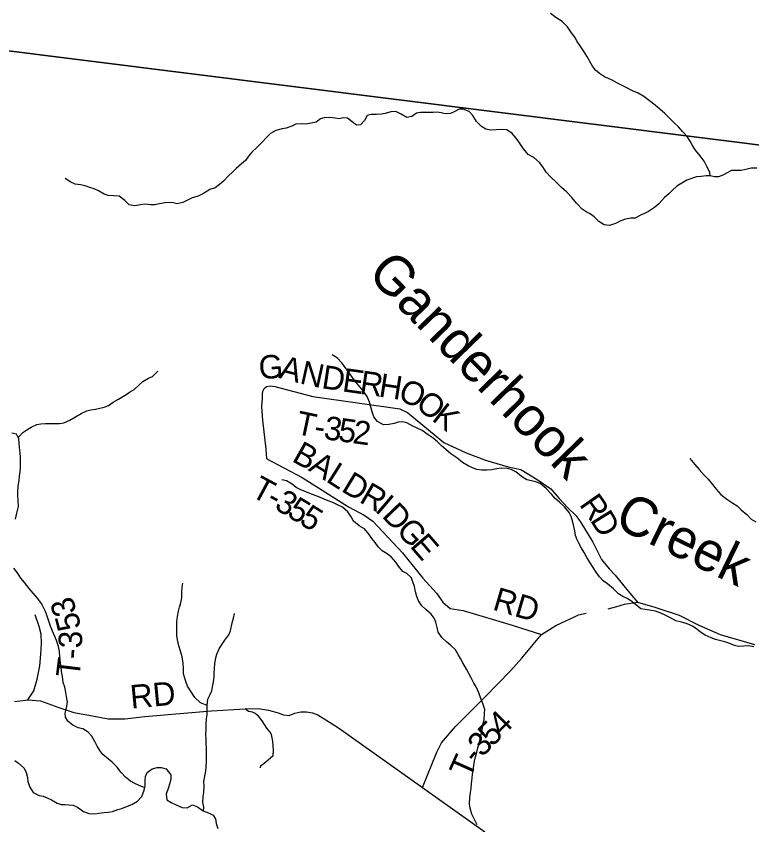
# Model space of a CAD drawing. Extents: x 1578669 to 1989827, y 208020 to 553079.
# Drawn here: x 1803566 to 1812953, y 353651 to 363967 of the extents above; entities that cross this region are included whole.
import ezdxf

# ---------------------------------------------------------------- set-up
doc = ezdxf.new("R2010")
doc.units = 0
for name, color, linetype in [('GM_X_County_Road', 7, 'Continuous'), ('GM_X_County_Road_Text', 7, 'Continuous'), ('GM_X_Minor_River', 7, 'Continuous'), ('GM_X_Minor_River_Text', 7, 'Continuous'), ('GM_X_Township', 7, 'Continuous'), ('GM_X_Township_Road', 7, 'Continuous'), ('GM_X_Township_Road_Text', 7, 'Continuous')]:
    doc.layers.add(name, color=color, linetype=linetype)

msp = doc.modelspace()

# ---------------------------------------------------------------- linework, layer by layer
at = {"layer": 'GM_X_County_Road'}
msp.add_lwpolyline([(1803546, 355225), (1803683, 355242), (1803715, 355245), (1803875, 355234), (1804112, 355146), (1804300, 355084), (1804541, 355040), (1804739, 355003), (1804952, 355003), (1805208, 355031), (1805656, 355072), (1806058, 355103), (1806488, 355130), (1806652, 355134), (1806786, 355114), (1806910, 355080), (1806979, 355056), (1807049, 355047), (1807123, 355074), (1807200, 355091), (1807272, 355093), (1807347, 355080), (1807415, 355056), (1807519, 354992), (1807680, 354890), (1808750, 354127), (1809548, 353563)], dxfattribs=at)
at = {"layer": 'GM_X_Minor_River'}
for points in [[(1812420, 361929), (1812418, 361975), (1812380, 362047), (1812344, 362119), (1812294, 362185), (1812236, 362257), (1812198, 362316), (1812166, 362374), (1812128, 362430), (1812068, 362496), (1812019, 362556), (1811963, 362606), (1811839, 362730), (1811785, 362776), (1811719, 362830), (1811647, 362888), (1811575, 362940), (1811503, 362984), (1811430, 363016), (1811350, 363058), (1811288, 363086), (1811238, 363114), (1811180, 363146), (1811124, 363170), (1811074, 363194), (1811010, 363236), (1810960, 363278), (1810922, 363330), (1810882, 363396), (1810848, 363456), (1810807, 363524), (1810771, 363576), (1810723, 363644), (1810695, 363698), (1810653, 363754), (1810599, 363829), (1810533, 363897), (1810451, 363949), (1810385, 363999)], [(1813015, 362028), (1812943, 362028), (1812893, 362016), (1812815, 361998), (1812765, 362000), (1812695, 361997), (1812639, 361967), (1812581, 361937), (1812529, 361919), (1812478, 361917), (1812420, 361929), (1812370, 361929), (1812306, 361923), (1812248, 361915), (1812194, 361901), (1812122, 361876), (1812058, 361838), (1811998, 361800), (1811946, 361750), (1811896, 361700), (1811840, 361654), (1811766, 361573), (1811712, 361527), (1811634, 361473), (1811584, 361451), (1811532, 361427), (1811464, 361390), (1811408, 361388), (1811341, 361378), (1811283, 361354), (1811213, 361320), (1811137, 361296), (1811069, 361306), (1811001, 361346), (1810943, 361408), (1810889, 361446), (1810839, 361470), (1810787, 361504), (1810715, 361580), (1810658, 361652), (1810594, 361720), (1810526, 361782), (1810456, 361850), (1810390, 361914), (1810328, 361978), (1810284, 362046), (1810244, 362102), (1810170, 362162), (1810101, 362202), (1810039, 362276), (1809987, 362352), (1809947, 362409), (1809895, 362469), (1809827, 362515), (1809761, 362520), (1809691, 362516), (1809619, 362514), (1809557, 362524), (1809502, 362558), (1809440, 362624), (1809392, 362698), (1809346, 362750), (1809268, 362780), (1809218, 362782), (1809164, 362752), (1809110, 362726), (1809040, 362722), (1808988, 362732), (1808938, 362740), (1808888, 362738), (1808832, 362736), (1808775, 362738), (1808725, 362739), (1808675, 362729), (1808613, 362687), (1808549, 362673), (1808477, 362717), (1808409, 362749), (1808347, 362747), (1808273, 362727), (1808223, 362717), (1808165, 362713), (1808097, 362712), (1808045, 362698), (1808011, 362634), (1807961, 362580), (1807909, 362576), (1807854, 362620), (1807792, 362666), (1807740, 362668), (1807688, 362658), (1807638, 362664), (1807570, 362672)], [(1807570, 362672), (1807498, 362670), (1807448, 362655), (1807392, 362613), (1807328, 362601), (1807258, 362587), (1807206, 362593), (1807134, 362589), (1807084, 362563), (1807013, 362539), (1806959, 362530), (1806879, 362508), (1806813, 362468), (1806755, 362416), (1806707, 362364), (1806643, 362297), (1806571, 362231), (1806531, 362181), (1806493, 362125), (1806441, 362081), (1806375, 362022), (1806325, 361978), (1806277, 361928), (1806211, 361860), (1806161, 361818), (1806105, 361778), (1806037, 361755), (1805957, 361705), (1805887, 361671), (1805813, 361649), (1805745, 361617), (1805693, 361589), (1805620, 361572), (1805570, 361584), (1805518, 361588), (1805466, 361584), (1805394, 361574), (1805336, 361560), (1805286, 361562), (1805206, 361568), (1805154, 361560), (1805082, 361548), (1805008, 361560), (1804954, 361614), (1804880, 361672), (1804807, 361676), (1804739, 361677), (1804687, 361697), (1804617, 361737), (1804561, 361763), (1804507, 361783), (1804447, 361801), (1804385, 361817), (1804317, 361823), (1804265, 361847), (1804193, 361895)], [(1808129, 358856), (1808109, 358918), (1808097, 358968), (1808073, 359043), (1808043, 359115), (1807995, 359189), (1807953, 359239), (1807909, 359291), (1807855, 359361), (1807805, 359431), (1807766, 359483), (1807720, 359545), (1807664, 359603), (1807598, 359647)], [(1803590, 358594), (1803606, 358605), (1803650, 358655), (1803700, 358688), (1803758, 358724), (1803830, 358756), (1803880, 358768), (1803938, 358770), (1804002, 358772), (1804069, 358770), (1804119, 358770), (1804173, 358778), (1804251, 358811), (1804323, 358857), (1804397, 358899), (1804467, 358931), (1804519, 358943), (1804579, 358953), (1804633, 358965), (1804689, 358978), (1804745, 359002), (1804805, 359042), (1804871, 359080), (1804955, 359130), (1805011, 359170), (1805071, 359203), (1805129, 359261), (1805183, 359307), (1805254, 359349), (1805306, 359369), (1805374, 359438)], [(1812979, 355921), (1812909, 355935), (1812849, 355929), (1812781, 355926), (1812731, 355938), (1812659, 355968), (1812607, 355986), (1812540, 356002), (1812488, 356014), (1812432, 356036), (1812356, 356072), (1812300, 356110), (1812250, 356146), (1812198, 356186), (1812128, 356214), (1812054, 356236), (1811984, 356254), (1811905, 356294), (1811855, 356322), (1811793, 356352), (1811723, 356378), (1811671, 356384), (1811591, 356396), (1811537, 356408), (1811485, 356448), (1811411, 356508), (1811361, 356538), (1811305, 356564), (1811251, 356596), (1811188, 356660), (1811112, 356724), (1811056, 356762), (1811010, 356814), (1810968, 356872), (1810930, 356932), (1810888, 356994), (1810846, 357060), (1810812, 357124), (1810778, 357182), (1810750, 357234), (1810723, 357287), (1810703, 357341), (1810693, 357403), (1810669, 357511), (1810647, 357583), (1810621, 357637), (1810563, 357707), (1810497, 357767), (1810443, 357815), (1810397, 357867), (1810329, 357941), (1810252, 358005), (1810196, 358025), (1810140, 358039), (1810084, 358051), (1810016, 358093), (1809940, 358155), (1809884, 358183), (1809832, 358195), (1809756, 358201), (1809698, 358191), (1809632, 358179), (1809571, 358173), (1809507, 358175), (1809443, 358185), (1809389, 358203), (1809335, 358229), (1809261, 358273), (1809187, 358331), (1809111, 358383), (1809049, 358439), (1808995, 358485), (1808940, 358537), (1808886, 358583), (1808822, 358627), (1808748, 358679), (1808684, 358711), (1808620, 358741), (1808550, 358779), (1808498, 358791), (1808440, 358787), (1808388, 358770), (1808320, 358756), (1808254, 358754), (1808175, 358796), (1808129, 358856)], [(1803559, 357551), (1803573, 357625), (1803597, 357713), (1803591, 357790), (1803585, 357846), (1803587, 357902), (1803592, 357968), (1803602, 358048), (1803610, 358100), (1803616, 358152), (1803622, 358214), (1803622, 358339), (1803616, 358395), (1803610, 358465), (1803606, 358523), (1803600, 358573), (1803570, 358635), (1803510, 358649)], [(1812162, 358323), (1812227, 358247), (1812283, 358183), (1812345, 358113), (1812395, 358061), (1812453, 357994), (1812499, 357934), (1812559, 357864), (1812635, 357804), (1812711, 357754), (1812764, 357722), (1812818, 357670), (1812890, 357608), (1812944, 357552), (1813006, 357514)], [(1809378, 354176), (1809384, 354244), (1809390, 354298), (1809398, 354350), (1809406, 354407), (1809416, 354461), (1809426, 354517), (1809442, 354577), (1809456, 354631), (1809474, 354691), (1809488, 354749), (1809500, 354805), (1809510, 354864), (1809520, 354924), (1809536, 354996), (1809543, 355072), (1809545, 355124), (1809521, 355198), (1809497, 355264), (1809469, 355333), (1809435, 355409), (1809407, 355459), (1809377, 355519), (1809343, 355581), (1809313, 355637), (1809267, 355719), (1809235, 355771), (1809207, 355823), (1809173, 355881), (1809106, 355941), (1809056, 355985), (1809002, 356037), (1808952, 356108), (1808938, 356166), (1808922, 356234), (1808900, 356288), (1808862, 356338), (1808794, 356398), (1808742, 356446), (1808700, 356510), (1808679, 356564), (1808663, 356622), (1808647, 356692), (1808627, 356750), (1808605, 356806), (1808551, 356855), (1808501, 356883), (1808443, 356949), (1808411, 357001), (1808351, 357071), (1808299, 357109), (1808235, 357147), (1808184, 357195), (1808148, 357253), (1808106, 357305), (1808070, 357355), (1808010, 357425), (1807944, 357465), (1807872, 357525), (1807842, 357579), (1807800, 357643), (1807730, 357701), (1807675, 357727), (1807613, 357757), (1807547, 357785), (1807497, 357807), (1807437, 357829), (1807379, 357853), (1807315, 357877), (1807261, 357899), (1807189, 357927), (1807139, 357955), (1807087, 357995), (1807016, 358037), (1806954, 358051)], [(1805208, 354127), (1805185, 354132), (1805135, 354154), (1805079, 354176), (1805025, 354208), (1804961, 354258), (1804904, 354320), (1804852, 354390), (1804792, 354452), (1804742, 354488), (1804672, 354546), (1804632, 354598), (1804600, 354654), (1804574, 354706), (1804530, 354782), (1804486, 354834), (1804416, 354876), (1804355, 354886), (1804291, 354920), (1804225, 354974), (1804197, 355026), (1804191, 355077), (1804207, 355143), (1804221, 355215), (1804209, 355287), (1804201, 355337), (1804185, 355405), (1804167, 355467), (1804155, 355543), (1804145, 355608), (1804139, 355666), (1804131, 355716), (1804123, 355792), (1804119, 355860), (1804108, 355924), (1804080, 356004), (1804058, 356054), (1804030, 356121), (1804006, 356183), (1803986, 356237), (1803970, 356289), (1803938, 356371), (1803914, 356423), (1803888, 356475), (1803838, 356541), (1803782, 356607), (1803732, 356667), (1803673, 356741), (1803627, 356799), (1803581, 356864), (1803537, 356924)], [(1806003, 355173), (1805917, 355207), (1805847, 355277), (1805799, 355347), (1805753, 355419), (1805725, 355490), (1805703, 355576), (1805699, 355644), (1805696, 355712), (1805684, 355792), (1805662, 355866), (1805640, 355934), (1805624, 356011), (1805616, 356067), (1805614, 356117), (1805614, 356171), (1805616, 356239), (1805624, 356309), (1805636, 356375), (1805650, 356427), (1805666, 356482), (1805678, 356546), (1805680, 356614), (1805684, 356684), (1805694, 356734)], [(1805958, 353826), (1805960, 353876), (1805948, 353937), (1805954, 354011), (1805962, 354063), (1805964, 354145), (1805962, 354203), (1805972, 354273), (1805984, 354337), (1805992, 354394), (1805996, 354448), (1805994, 354506), (1805994, 354626), (1805992, 354694), (1805989, 354754), (1805987, 354804), (1805989, 354873), (1805989, 354925), (1805995, 355001), (1806001, 355053), (1806003, 355129), (1806003, 355179), (1806013, 355253), (1806039, 355304), (1806061, 355360), (1806073, 355410), (1806085, 355474), (1806091, 355538), (1806093, 355590), (1806097, 355642), (1806101, 355709), (1806113, 355779), (1806125, 355829), (1806161, 355905), (1806193, 355955), (1806229, 356005), (1806279, 356074), (1806301, 356126), (1806321, 356226), (1806339, 356288), (1806353, 356348)], [(1803547, 354472), (1803597, 354436), (1803667, 354372), (1803695, 354318), (1803709, 354256), (1803713, 354204), (1803741, 354132), (1803783, 354062), (1803859, 354024), (1803912, 354016), (1803962, 353996), (1804016, 353968), (1804090, 353926), (1804140, 353912), (1804190, 353908), (1804242, 353906), (1804294, 353900), (1804350, 353874), (1804424, 353822), (1804492, 353796), (1804566, 353792), (1804620, 353800), (1804689, 353809), (1804739, 353813), (1804795, 353821), (1804865, 353847), (1804915, 353861), (1804967, 353881), (1805041, 353911), (1805115, 353951), (1805169, 354010), (1805201, 354094), (1805213, 354148), (1805213, 354216), (1805217, 354268), (1805239, 354318), (1805301, 354365), (1805367, 354381), (1805417, 354381), (1805481, 354363), (1805539, 354287), (1805541, 354237), (1805527, 354183), (1805505, 354114), (1805481, 354042), (1805489, 353968), (1805545, 353936), (1805614, 353900), (1805682, 353872), (1805746, 353868), (1805814, 353906), (1805880, 353882), (1805950, 353828), (1806020, 353804), (1806078, 353776), (1806110, 353726), (1806118, 353668), (1806140, 353604)], [(1809450, 353649), (1809414, 353719), (1809382, 353787), (1809358, 353863), (1809350, 353917), (1809356, 353998), (1809364, 354064), (1809370, 354116), (1809378, 354176)]]:
    msp.add_lwpolyline(points, dxfattribs=at)
at = {"layer": 'GM_X_Township'}
for points in [[(1795322, 364551), (1813574, 362259)], [(1816277, 364043), (1816631, 363924), (1816735, 363905), (1816837, 363873), (1816931, 363836), (1817131, 363727), (1817227, 363665), (1817520, 363444), (1817577, 363353), (1817650, 363170), (1817685, 362949), (1817688, 362852), (1817672, 362762), (1817667, 362662), (1817645, 362376), (1817518, 361992), (1817360, 361758), (1813574, 362259), (1795322, 364551)]]:
    msp.add_lwpolyline(points, dxfattribs=at)
at = {"layer": 'GM_X_Township_Road'}
for points in [[(1806765, 358318), (1806754, 358442), (1806715, 358812), (1806702, 358987), (1806707, 359095), (1806709, 359153), (1806719, 359191), (1806732, 359217), (1806760, 359241), (1806808, 359251), (1806866, 359242), (1807351, 359114), (1808463, 358959), (1808559, 358910), (1809022, 358529), (1809307, 358397), (1809553, 358301), (1809842, 358218), (1810006, 358185), (1810212, 358057), (1810390, 357935), (1810494, 357812), (1810599, 357699), (1810713, 357591), (1810771, 357507), (1810923, 357255), (1811034, 357037), (1811132, 356916), (1811210, 356835), (1811375, 356631), (1811494, 356492), (1811715, 356426), (1812026, 356325), (1812278, 356197), (1812550, 356080), (1812987, 355951)], [(1806765, 358318), (1807216, 358082), (1807807, 357708), (1808006, 357602), (1808117, 357525), (1808496, 357121), (1808755, 356796), (1808928, 356604), (1809008, 356491), (1809104, 356410), (1809268, 356383), (1809894, 356199), (1810268, 356080)], [(1811118, 356405), (1811230, 356438), (1811330, 356466), (1811494, 356492)], [(1803715, 355245), (1803792, 355359), (1803833, 355507), (1803869, 355680), (1803880, 355826), (1803891, 355962), (1803885, 356085), (1803860, 356179), (1803807, 356328)], [(1808750, 354127), (1808934, 354577), (1808991, 354697), (1809173, 354903), (1809546, 355281), (1809875, 355617), (1810017, 355775), (1810141, 355924), (1810268, 356080), (1810404, 356164), (1810453, 356193), (1810581, 356251), (1810690, 356303), (1810743, 356329), (1810840, 356351)], [(1806685, 354377), (1806689, 354408), (1806707, 354420), (1806732, 354437), (1806782, 354478), (1806844, 354534), (1806850, 354598), (1806840, 354720), (1806825, 354801), (1806805, 354832), (1806763, 354884), (1806703, 354977), (1806660, 355039), (1806616, 355070), (1806583, 355087), (1806532, 355095), (1806488, 355130)]]:
    msp.add_lwpolyline(points, dxfattribs=at)

# ---------------------------------------------------------------- texts
at = {"layer": 'GM_X_County_Road_Text'}
msp.add_text('RD', height=300, rotation=5.4198, dxfattribs=at).set_placement((1805034, 355132))
at = {"layer": 'GM_X_Minor_River_Text'}
for s, rotation, p in [('Ganderhook', 314.1517, (1808032, 360671)), ('Creek', 334.0199, (1811177, 357464))]:
    msp.add_text(s, height=500, rotation=rotation, dxfattribs=at).set_placement(p)
at = {"layer": 'GM_X_Township_Road_Text'}
for s, rotation, p in [('G', 3.2037, (1806668, 359336)), ('A', 345.4743, (1806907, 359353)), ('N', 347.398, (1807173, 359284)), ('D', 351.3468, (1807453, 359222)), ('E', 351.9067, (1807717, 359182)), ('R', 351.898, (1807939, 359151)), ('H', 351.1384, (1808182, 359116)), ('O', 336.2887, (1808423, 359081)), ('O', 321.2953, (1808647, 358986)), ('K', 322.0273, (1808857, 358818)), ('T', 348.1387, (1807119, 358641)), ('3', 351.8601, (1807481, 358573)), ('5', 352.1122, (1807665, 358547)), ('2', 352.1693, (1807849, 358521)), ('-', 351.3531, (1807356, 358592)), ('B', 330.6482, (1807071, 358296)), ('A', 328.241, (1807283, 358177)), ('L', 327.633, (1807506, 358038)), ('T', 331.7309, (1806545, 357851)), ('D', 328.7484, (1807701, 357915)), ('R', 329.6196, (1807931, 357775)), ('3', 330.0118, (1806848, 357687)), ('I', 319.6307, (1808133, 357658)), ('R', 305.0368, (1810743, 357737)), ('-', 331.1198, (1806742, 357745)), ('5', 328.7051, (1807007, 357595)), ('D', 313.8975, (1808221, 357584)), ('5', 327.9036, (1807164, 357500)), ('D', 301.8934, (1810882, 357539)), ('G', 312.7687, (1808403, 357395)), ('E', 310.8082, (1808580, 357203)), ('RD', 343.5845, (1809632, 356399)), ('3', 108.6898, (1804345, 356371)), ('5', 104.2104, (1804398, 356168)), ('3', 90.039, (1804408, 355903)), ('-', 85.7738, (1804398, 355756)), ('T', 83.1349, (1804370, 355518)), ('4', 45.3348, (1809769, 354768)), ('5', 45.4857, (1809640, 354637)), ('3', 46.3469, (1809513, 354504)), ('T', 65.8621, (1809356, 354228)), ('-', 49.3039, (1809435, 354414))]:
    msp.add_text(s, height=300, rotation=rotation, dxfattribs=at).set_placement(p)

doc.saveas('drawing.dxf')
